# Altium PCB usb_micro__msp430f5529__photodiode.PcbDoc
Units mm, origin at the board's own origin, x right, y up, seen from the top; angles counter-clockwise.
Board outline 62 x 34 mm, 2 copper layers (Top, Bottom), stack 0 mm thick; 25 components, 18 nets, 155 pads, 46 vias.
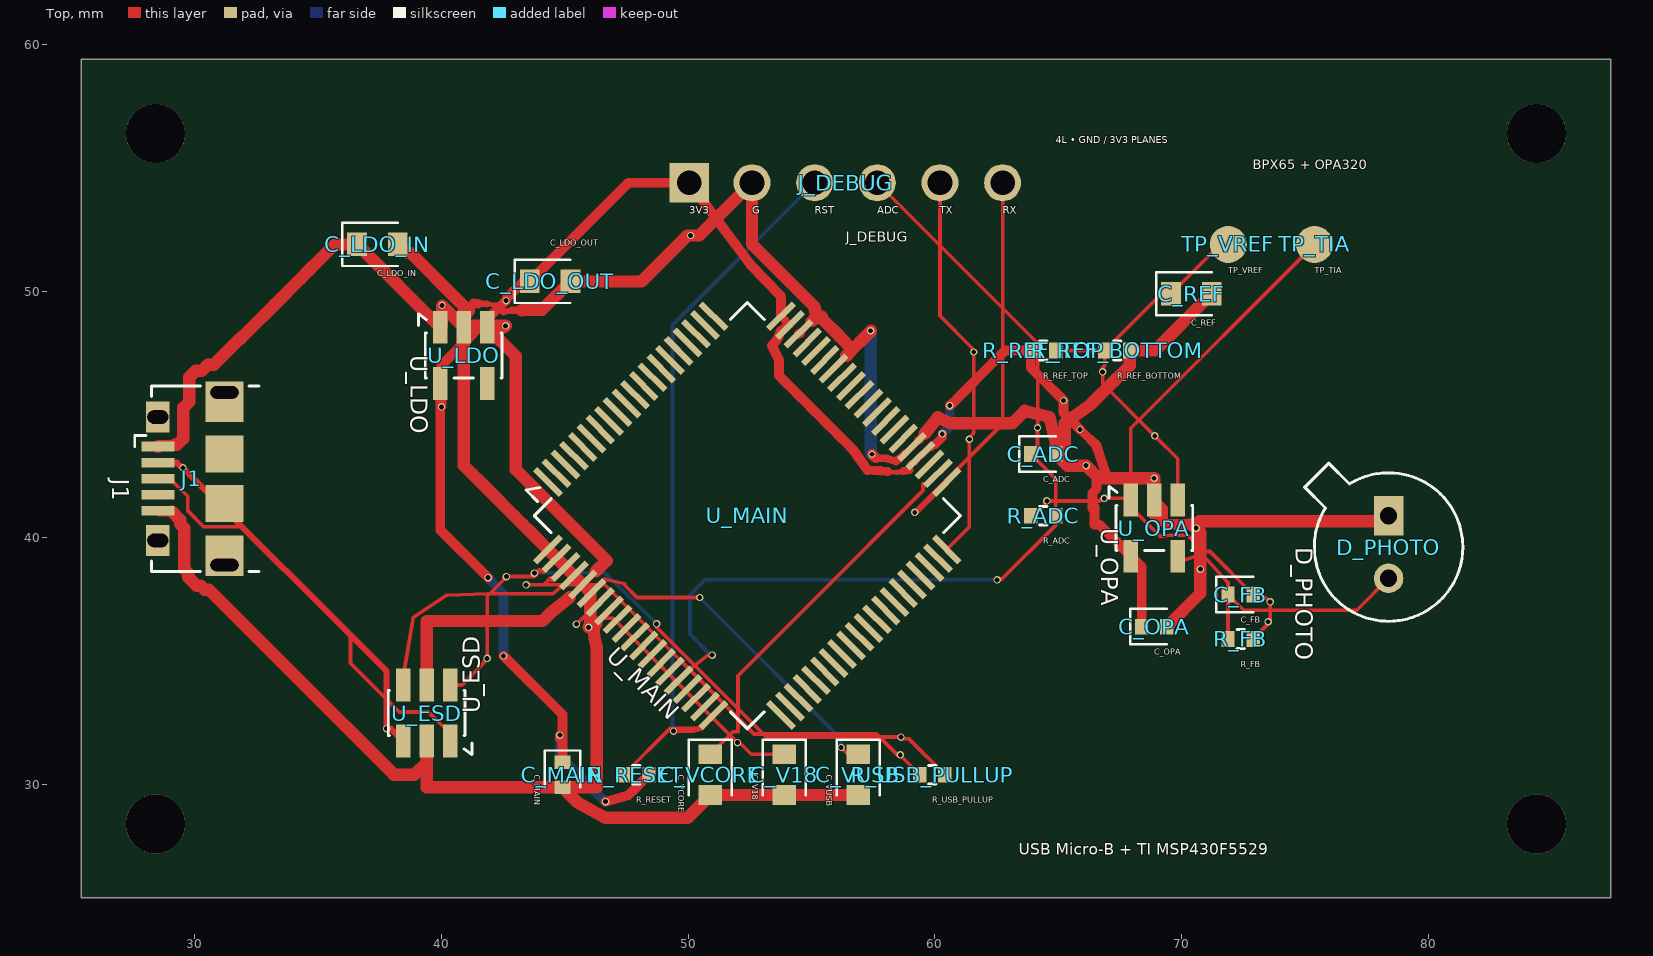
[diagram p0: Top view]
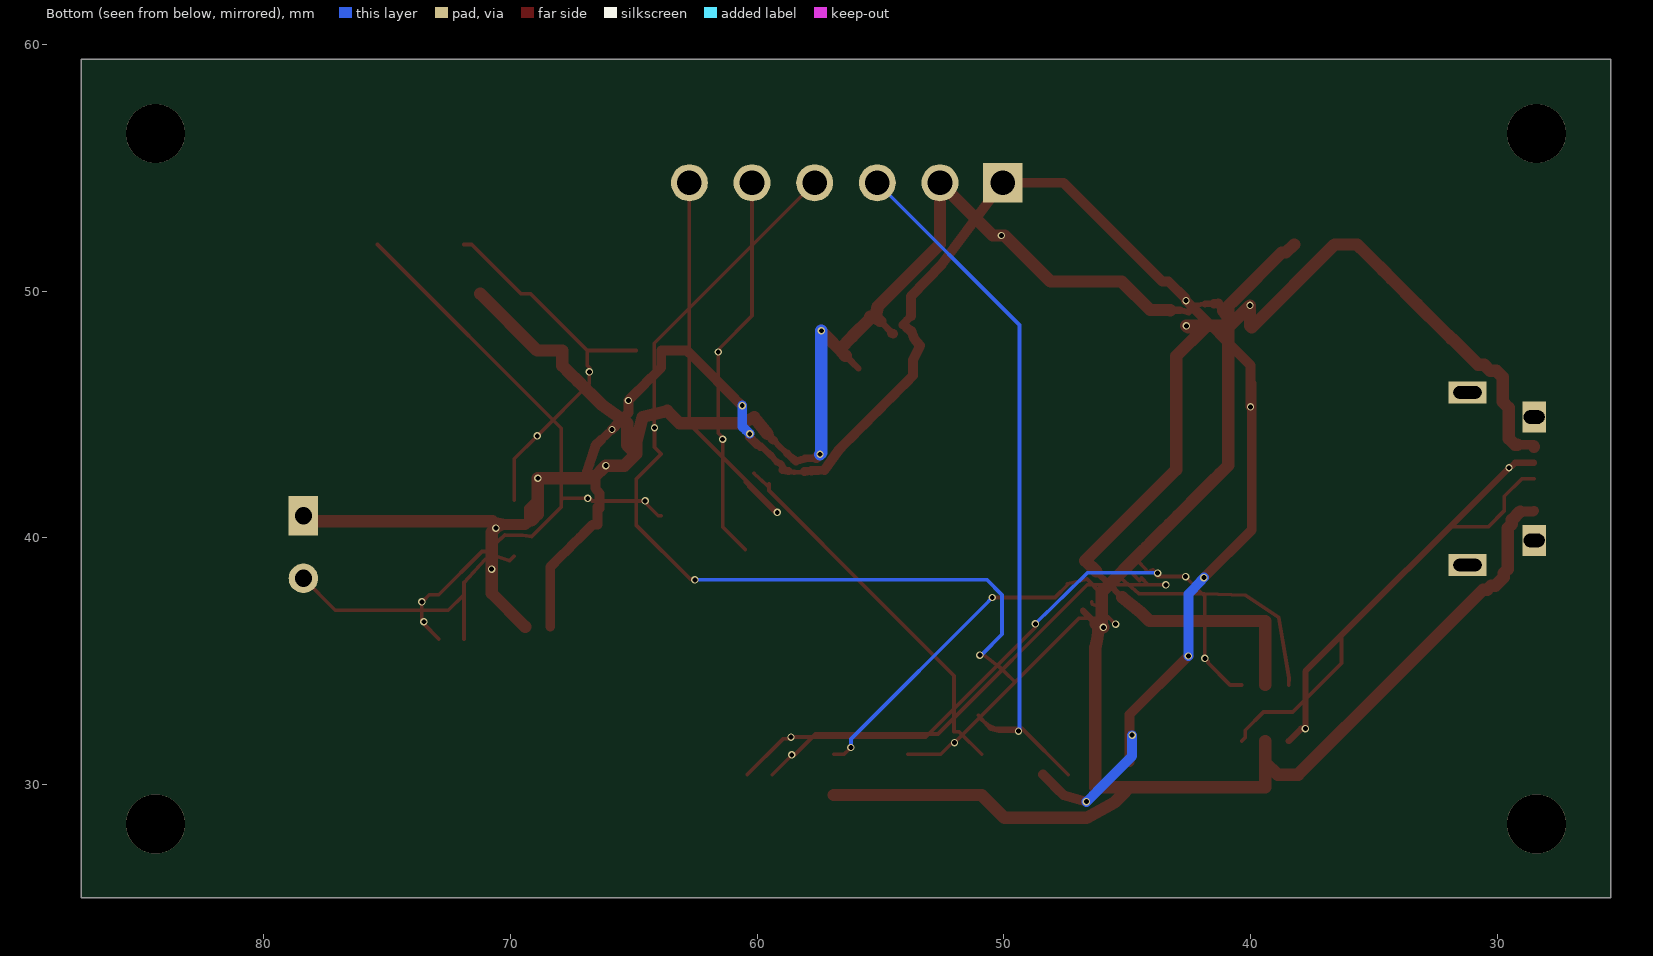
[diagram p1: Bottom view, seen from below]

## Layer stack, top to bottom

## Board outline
25.4,59.4 87.4,59.4 87.4,25.4 25.4,25.4

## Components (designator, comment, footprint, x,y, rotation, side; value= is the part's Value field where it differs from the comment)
C_ADC "" TSCIRCUIT-1.5600x0.6400mm 64.4,43.4 r0 top
C_FB "" TSCIRCUIT-1.5600x0.6400mm 72.4,37.7 r0 top
C_LDO_IN "" TSCIRCUIT-2.4500x0.9500mm 37.4,51.9 r0 top
C_LDO_OUT "" TSCIRCUIT-2.4500x0.9500mm 44.4,50.4 r0 top
C_MAIN "" TSCIRCUIT-0.6400x1.5600mm 44.9,30.4 r270 top
C_OPA "" TSCIRCUIT-1.5600x0.6400mm 68.9,36.4 r0 top
C_REF "" TSCIRCUIT-2.4500x0.9500mm 70.4,49.9 r0 top
C_V18 "" TSCIRCUIT-0.9500x2.4500mm 53.9,30.4 r270 top
C_VCORE "" TSCIRCUIT-0.9500x2.4500mm 50.9,30.4 r270 top
C_VUSB "" TSCIRCUIT-0.9500x2.4500mm 56.9,30.4 r270 top
D_PHOTO "" TSCIRCUIT-1.2000x3.9400mm 78.4,39.73 r270 top
J1 "" TSCIRCUIT-4.1500x7.8900mm 29.9,42.4 r270 top
J_DEBUG "" TSCIRCUIT-14.2000x1.5000mm 56.4,54.4 r0 top
R_ADC "" TSCIRCUIT-1.5600x0.6400mm 64.4,40.9 r0 top
R_FB "" TSCIRCUIT-1.5600x0.6400mm 72.4,35.9 r0 top
R_REF_BOTTOM "" TSCIRCUIT-1.5600x0.6400mm 67.4,47.6 r0 top
R_REF_TOP "" TSCIRCUIT-1.5600x0.6400mm 64.4,47.6 r0 top
R_RESET "" TSCIRCUIT-1.5600x0.6400mm 47.9,30.4 r0 top
R_USB_PULLUP "" TSCIRCUIT-1.5600x0.6400mm 59.9,30.4 r0 top
TP_TIA "" TSCIRCUIT-1.5000x1.5000mm 75.4,51.9 r0 top
TP_VREF "" TSCIRCUIT-1.5000x1.5000mm 71.9,51.9 r0 top
U_ESD "" TSCIRCUIT-2.5000x3.6000mm#1 39.4,32.9 r90 top
U_LDO "" TSCIRCUIT-2.5000x3.6000mm#2 40.9,47.4 r270 top
U_MAIN "" TSCIRCUIT-17.3948x17.3948mm 52.4,40.9 r315 top
U_OPA "" TSCIRCUIT-2.5000x3.6000mm#2 68.9,40.4 r270 top

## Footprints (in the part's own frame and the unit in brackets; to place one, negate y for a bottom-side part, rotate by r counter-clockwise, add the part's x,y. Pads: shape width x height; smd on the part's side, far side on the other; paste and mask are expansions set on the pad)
TSCIRCUIT-0.6400x1.5600mm [mm]
  rect 0.54x0.64 smd: 1(-0.51,0) 2(0.51,0)
  silkscreen extent -0.98,-0.72 0.51,0.72
TSCIRCUIT-0.9500x2.4500mm [mm]
  rect 0.8x0.95 smd: 1(-0.825,0) 2(0.825,0)
  silkscreen extent -1.43,-0.87 0.82,0.88
TSCIRCUIT-1.2000x3.9400mm [mm]
  rect 1.6x1.2 hole 0.7: 1(-1.17,0)
  round 1.2 hole 0.7: 2(1.37,0)
  silkscreen extent -3.3,-3.4 3.11,3.01
TSCIRCUIT-1.5000x1.5000mm [mm]
  round 1.5 smd: 1(0,0)
TSCIRCUIT-1.5600x0.6400mm [mm]
  rect 0.54x0.64 smd: 1(-0.51,0) 2(0.51,0)
  silkscreen extent -0.98,-0.72 0.51,0.72
TSCIRCUIT-2.4500x0.9500mm [mm]
  rect 0.8x0.95 smd: 1(-0.825,0) 2(0.825,0)
  silkscreen extent -1.42,-0.87 0.83,0.87
TSCIRCUIT-2.5000x3.6000mm#1 [mm]
  rect 1.325x0.6 smd: 1(-1.138,-0.95) 2(-1.138,0) 3(-1.138,0.95) 4(1.138,0.95) 5(1.138,0) 6(1.138,-0.95)
  silkscreen extent -1.69,-1.84 0.91,1.56
TSCIRCUIT-2.5000x3.6000mm#2 [mm]
  rect 1.325x0.6 smd: 1(-1.138,-0.95) 2(-1.138,0) 3(-1.138,0.95) 4(1.137,0.95) 5(1.137,-0.95)
  silkscreen extent -1.69,-1.84 0.91,1.56
TSCIRCUIT-4.1500x7.8900mm [mm]
  rect 0.89x1.55 hole 0.5 slot 1.15 at 90 deg: 1(-3.5,1.3) 1(3.5,1.3)
  rect 1.45x1.55 smd: 1(-3.025,1.3) 1(3.025,1.3)
  rect 1.25x0.95 hole 0.55 slot 0.85 at 90 deg: 1(-2.5,-1.4) 1(2.5,-1.4)
  rect 0.4x1.35 smd: 1(-1.3,-1.4) 2(-0.65,-1.4) 3(0,-1.4) 4(0.65,-1.4) 5(1.3,-1.4)
  rect 1.5x1.55 smd: 1(-1,1.3) 1(1,1.3)
  silkscreen extent -3.76,-2.34 3.76,2.69
TSCIRCUIT-14.2000x1.5000mm [mm]
  rect 1.6x1.6 hole 1: 1(-6.35,0)
  round 1.5 hole 1: 2(-3.81,0) 3(-1.27,0) 4(1.27,0) 5(3.81,0) 6(6.35,0)
TSCIRCUIT-17.3948x17.3948mm [mm]
  rect 1.475x0.25 smd: 1(-6.687,-4.75) 2(-6.687,-4.25) 3(-6.687,-3.75) 4(-6.687,-3.25) 5(-6.687,-2.75) 6(-6.687,-2.25) 7(-6.687,-1.75) 8(-6.687,-1.25) 9(-6.687,-0.75) 10(-6.687,-0.25) 11(-6.687,0.25) 12(-6.687,0.75) 13(-6.687,1.25) 14(-6.687,1.75) 15(-6.687,2.25) 16(-6.687,2.75) 17(-6.687,3.25) 18(-6.687,3.75) 19(-6.687,4.25) 20(-6.687,4.75) 41(6.688,4.75) 42(6.687,4.25) 43(6.687,3.75) 44(6.687,3.25) 45(6.688,2.75) 46(6.687,2.25) 47(6.687,1.75) 48(6.687,1.25) 49(6.687,0.75) 50(6.687,0.25) 51(6.687,-0.25) 52(6.687,-0.75) 53(6.687,-1.25) 54(6.687,-1.75) 55(6.687,-2.25) 56(6.687,-2.75) 57(6.687,-3.25) 58(6.687,-3.75) 59(6.687,-4.25) 60(6.687,-4.75)
  rect 0.25x1.475 smd: 21(-4.75,6.688) 22(-4.25,6.687) 23(-3.75,6.687) 24(-3.25,6.688) 25(-2.75,6.688) 26(-2.25,6.687) 27(-1.75,6.687) 28(-1.25,6.688) 29(-0.75,6.688) 30(-0.25,6.687) 31(0.25,6.687) 32(0.75,6.688) 33(1.25,6.688) 34(1.75,6.687) 35(2.25,6.687) 36(2.75,6.688) 37(3.25,6.688) 38(3.75,6.687) 39(4.25,6.687) 40(4.75,6.688) 61(4.75,-6.687) 62(4.25,-6.687) 63(3.75,-6.687) 64(3.25,-6.687) 65(2.75,-6.687) 66(2.25,-6.687) 67(1.75,-6.687) 68(1.25,-6.687) 69(0.75,-6.687) 70(0.25,-6.687) 71(-0.25,-6.687) 72(-0.75,-6.687) 73(-1.25,-6.687) 74(-1.75,-6.687) 75(-2.25,-6.687) 76(-2.75,-6.687) 77(-3.25,-6.687) 78(-3.75,-6.687) 79(-4.25,-6.687) 80(-4.75,-6.687)
  silkscreen extent -7.09,-6.11 6.11,6.11

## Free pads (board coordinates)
  round 2.4 hole 2.4 unplated: NPTH-1(28.4,28.4) NPTH-2(84.4,56.4) NPTH-3(84.4,28.4) NPTH-4(28.4,56.4)

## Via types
v1: diameter 0.3, hole 0.2, Top to Bottom, 46 vias

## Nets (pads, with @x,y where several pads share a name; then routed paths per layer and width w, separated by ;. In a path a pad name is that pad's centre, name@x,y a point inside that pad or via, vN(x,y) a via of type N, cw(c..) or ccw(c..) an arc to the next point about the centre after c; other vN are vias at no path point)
ADC_IN: C_ADC.1 J_DEBUG.4 R_ADC.2 U_MAIN.65 | length 37.7
  Top w0.15: U_MAIN.65 50.157,34.748 50.812,35.246 v1(50.972,35.246) ; J_DEBUG.4 64.179,47.891 64.179,44.528 64.179,44.481 v1(64.164,44.466) 64.164,43.674 C_ADC.1 64.91,42.38 R_ADC.2 64.91,40.526 62.719,38.336 62.562,38.336 v1(62.527,38.301)
  Bottom w0.15: v1(50.972,35.246) 50.941,35.277 50.888,35.277 50.073,36.091 50.073,37.689 50.686,38.301 v1(62.527,38.301)
GND: C_ADC.2 C_LDO_IN.2 C_LDO_OUT.2 C_MAIN.2 C_OPA.2 C_REF.2 C_V18.2 C_VCORE.2 C_VUSB.2 D_PHOTO.1 J1.5 J_DEBUG.2 R_REF_BOTTOM.2 U_ESD.2 U_LDO.2 U_MAIN.23 U_MAIN.27 U_MAIN.36 U_MAIN.73 U_MAIN.80 U_OPA.2 | length 142.4
  Top w0.2: 41.842,49.489 42.2,49.45 42.5,49.15
  Top w0.25: 42.5,49.15 42.852,49.232 ; 44.224,39.618 U_MAIN.80 ; U_MAIN.73@46.275,36.543 U_MAIN.73 ; U_MAIN.23 U_MAIN.23@54.982,48.785 ; U_MAIN.27@56.162,47.126 U_MAIN.27 U_MAIN.27@56.413,47.388 ; U_MAIN.36@58.794,43.428 U_MAIN.36 U_MAIN.36@59.339,43.95
  Top w0.251: U_MAIN.23@54.544,48.299 54.601,48.367 54.899,48.665 U_MAIN.23@55.017,48.783
  Top w0.257: U_MAIN.73@46.275,36.524 46.533,36.779 U_MAIN.73
  Top w0.275: 41.482,49.492 41.842,49.489
  Top w0.278: U_MAIN.27@56.162,47.126 56.432,47.386
  Top w0.3: 42.852,49.232 43.259,49.236
  Top w0.314: U_MAIN.36@58.526,43.188 U_MAIN.36@58.794,43.428
  Top w0.325: 57.597,43.248 58.056,43.21 58.431,43.103 58.526,43.188
  Top w0.345: U_MAIN.36@59.339,43.95 59.35,43.95 U_MAIN.36@59.525,44.15
  Top w0.375: 41.103,49.218 41.306,49.525 41.482,49.492 ; 69.247,40.681 69.525,40.525 69.994,40.525
  Top w0.389: U_MAIN.23 U_MAIN.23@54.544,48.299
  Top w0.397: U_MAIN.36@59.525,44.15 U_MAIN.36@59.581,44.219
  Top w0.4: J1.5 28.533,41.067 J1.5@29.067,41.067 ; U_OPA.2 69.247,41.19 69.247,40.936 69.247,40.681 ; 69.994,40.525 70.736,40.681
  Top w0.425: v1(57.456,43.392) 57.597,43.248
  Top w0.437: U_MAIN.23@54.982,48.785 55.029,48.785 55.416,48.963 ; 69.15,40.712 69.416,40.541 70.291,40.541
  Top w0.45: 70.291,40.541 v1(70.6,40.4)
  Top w0.475: 55.017,48.783 55.197,48.963
  Top w0.5: J1.5@29.067,41.067 29.4,40.733 29.4,40.567 29.567,40.4 29.567,38.733 29.733,38.567 29.733,38.4 30.067,38.067 30.233,38.067 30.4,37.9 30.567,37.9 34.129,34.337 38.067,30.4 38.9,30.4 39.4,30.9 U_ESD.2 39.4,29.89 C_MAIN.2 ; C_LDO_IN.2 38.565,51.571 38.729,51.571 40.65,49.65 40.9,49.4 U_LDO.2 ; 41.103,49.218 40.9,48.91 U_LDO.2 ; 43.259,49.236 43.665,49.241 44.066,49.241 C_LDO_OUT.2 48.106,50.4 49.968,52.262 v1(50.1,52.262) 50.452,52.262 J_DEBUG.2 52.59,51.905 55.112,49.383 55.197,48.963 ; 44.224,39.618 43.971,39.871 43.63,40.212 43.289,40.554 42.947,40.895 42.606,41.236 42.265,41.577 41.924,41.919 41.582,42.26 41.241,42.601 40.9,42.942 40.9,43.409 40.9,43.875 40.9,44.341 40.9,44.807 40.9,45.274 40.9,45.74 40.9,46.206 40.9,46.672 40.9,47.139 40.9,47.605 40.9,48.071 U_LDO.2 ; U_MAIN.80 46.025,37.817 46.025,36.4 v1(45.965,36.374) 46.275,36.525 U_MAIN.73@46.275,36.543 ; 46.275,36.524 46.15,36.4 46.206,35.957 46.292,35.566 46.299,35.097 46.299,29.89 C_MAIN.2 ; 55.416,48.963 55.416,48.897 56.152,48.161 56.65,47.65 56.432,47.386 ; 56.413,47.388 57.4,48.375 v1(57.4,48.4) ; C_VUSB.2 C_V18.2 C_VCORE.2 49.975,28.65 46.65,28.65 45.513,29.273 45.206,29.581 C_MAIN.2 ; 59.581,44.219 60.126,44.887 60.65,44.65 63.15,44.65 63.65,45.15 64.65,44.9 64.91,43.825 C_ADC.2 ; 69.15,40.712 68.9,40.963 U_OPA.2 68.9,42.411 v1(68.893,42.418) 66.651,42.418 v1(66.139,42.93) 65.38,42.93 C_ADC.2 ; C_OPA.2 70.766,37.756 v1(70.766,38.733) 70.766,40.234 v1(70.6,40.4) ; 70.736,40.681 71.232,40.681 71.729,40.681 72.225,40.681 72.721,40.681 73.218,40.681 73.714,40.681 74.21,40.681 74.707,40.681 75.203,40.681 75.699,40.681 76.196,40.681 76.692,40.681 77.189,40.681 77.685,40.681 78.181,40.681 D_PHOTO.1 ; C_REF.2 68.925,47.6 R_REF_BOTTOM.2 67.909,47.292 67.908,46.983 67.589,46.67 67.271,46.357 66.953,46.043 66.634,45.73 66.316,45.416 65.275,44.65 65.275,43.765 C_ADC.2
  Bottom w0.5: v1(57.4,48.4) 57.4,47.914 57.4,47.428 57.4,46.942 57.4,46.457 57.4,45.971 57.4,45.485 57.4,44.999 57.4,44.513 57.4,44.027 57.4,43.542 57.4,43.448 v1(57.456,43.392)
MAIN_RESET: J_DEBUG.3 R_RESET.1 U_MAIN.61 | length 31.2
  Top w0.15: R_RESET.1 49.264,32.274 50.358,32.274 50.359,32.286 50.578,32.38 50.983,32.67 50.96,32.742 U_MAIN.61 50.533,32.248 50.205,32.164 v1(49.406,32.164)
  Bottom w0.15: v1(49.406,32.164) 49.365,32.205 49.365,32.289 49.365,48.635 J_DEBUG.3
MSP_USB_PUR: R_USB_PULLUP.1 U_MAIN.78 | length 21.2
  Top w0.15: U_MAIN.78 44.499,38.26 44.42,38.372 44.147,38.1 43.558,38.1 v1(43.428,38.094) 46.62,38.1 52.67,32.051 57.634,32.051 58.485,31.2 v1(58.6,31.2) 58.6,31.19 R_USB_PULLUP.1
MSP_V18: C_V18.1 U_MAIN.74 | length 12.2
  Top w0.15: U_MAIN.74 46.419,37.31 46.234,37.249 45.796,36.808 v1(45.466,36.502) 45.585,36.597 45.585,36.608 45.723,36.747 45.765,36.747 46.95,36.747 v1(52,31.697) 52.004,31.693 52.094,31.693 52.562,31.225 C_V18.1
MSP_VCORE: C_VCORE.1 U_MAIN.39 | length 15.5
  Top w0.15: C_VCORE.1 51.817,32.142 52.019,32.142 52.019,34.414 55.12,37.515 59.523,41.918 59.525,42.184 59.58,42.116 U_MAIN.39
MSP_VUSB: C_VUSB.1 U_MAIN.75 | length 14.2
  Top w0.15: U_MAIN.75 46.625,38.332 47.415,38.135 47.412,38.101 47.929,37.583 v1(50.469,37.583) ; v1(56.2,31.5) 56.244,31.456 56.246,31.456 56.476,31.225 C_VUSB.1
  Bottom w0.15: v1(50.469,37.583) 50.613,37.439 50.613,37.435 56.2,31.848 v1(56.2,31.5)
PD_SUM: C_FB.1 D_PHOTO.2 R_FB.1 U_OPA.4 | length 12.2
  Top w0.15: U_OPA.4 70.041,39.072 70.575,39.25 71.025,39.138 71.89,38.188 C_FB.1 ; R_FB.1 C_FB.1 ; D_PHOTO.2 77.106,37.065 72.627,37.063 72.524,37.066 C_FB.1
TIA_OUT: C_FB.2 R_ADC.1 R_FB.2 TP_TIA.1 U_OPA.1 | length 27.2
  Top w0.15: R_ADC.1 64.016,40.9 64.457,41.341 64.457,41.412 v1(64.544,41.499) 66.679,41.499 66.76,41.58 66.823,41.58 v1(66.871,41.603) 67.884,41.603 U_OPA.1 ; R_FB.2 73.515,36.505 v1(73.515,36.601) 73.557,36.643 73.557,36.669 73.6,36.713 v1(73.6,37.404) 73.556,37.444 73.554,37.444 73.298,37.7 C_FB.2 71.159,39.451 70.959,39.451 70.233,40.114 69.515,40.107 69.141,40.058 67.95,41.249 U_OPA.1 ; TP_TIA.1 67.95,44.45 U_OPA.1
UART_MAIN_RX: J_DEBUG.6 U_MAIN.40 | length 16.7
  Top w0.15: U_MAIN.40 60.339,42.122 60.342,42.08 59.292,41.036 v1(59.188,41.036) 59.234,41.081 59.234,41.106 62.75,44.622 J_DEBUG.6
UART_MAIN_TX: J_DEBUG.5 U_MAIN.41 | length 15.9
  Top w0.15: J_DEBUG.5 60.21,49.005 61.521,47.693 61.521,47.597 v1(61.58,47.538) 61.58,44.253 61.429,44.102 61.429,44.029 v1(61.4,44) 61.4,40.442 U_MAIN.41
USB_DM_MCU: U_ESD.4 U_MAIN.77 | length 9.8
  Top w0.15: U_ESD.4 38.439,34.311 38.85,36.775 40.2,37.675 41.886,37.74 44.526,37.738 U_MAIN.77
USB_DM_PORT: J1.2 U_ESD.3 | length 16
  Top w0.25: J1.2 29.273,43.05 29.433,42.89 29.471,42.89 v1(29.516,42.845) 37.775,34.586 37.775,32.379 v1(37.775,32.265) 37.947,32.265 U_ESD.3
USB_DP_MCU: R_USB_PULLUP.2 U_ESD.6 U_MAIN.79 | length 29.4
  Top w0.15: U_ESD.6 40.825,34.038 41.726,34.938 41.726,34.99 v1(41.85,35.114) 41.85,37.633 42.543,38.326 42.543,38.344 v1(42.629,38.432) 43.762,38.434 44.02,38.688 44.145,38.613 ; v1(43.765,38.572) 43.818,38.572 43.955,38.709 44.145,38.613 ; v1(48.723,36.516) 48.723,36.477 48.723,36.368 53.167,31.924 v1(58.631,31.924) 58.704,31.851 58.761,31.851 58.959,31.851 R_USB_PULLUP.2 ; 44.145,38.613 U_MAIN.79 44.145,38.613
  Bottom w0.15: v1(43.765,38.572) 43.776,38.583 43.888,38.583 46.617,38.583 v1(48.723,36.516)
USB_DP_PORT: J1.3 U_ESD.1 | length 17.5
  Top w0.15: J1.3 28.994,42.4 29.705,41.689 29.705,41.11 30.352,40.454 31.962,40.459 36.306,36.115 36.306,34.919 38.288,32.937 39.472,32.937 40.209,32.201 40.209,31.903 U_ESD.1
VBUS5: C_LDO_IN.1 J1.1@28.5,43.7 U_ESD.5 U_LDO.1 U_LDO.3 U_MAIN.76 | length 44.5
  Top w0.25: U_MAIN.76@45.275,37.65 U_MAIN.76 U_MAIN.76@46.248,38.637
  Top w0.273: U_MAIN.76@45.205,37.594 U_MAIN.76@45.275,37.65
  Top w0.4: J1.1@28.525,43.725 28.525,43.775 29.175,43.775
  Top w0.5: J1.1@28.5,43.7 J1.1@28.525,43.725 ; 29.175,43.775 29.275,43.775 29.525,44.025 29.525,45.275 29.775,45.525 29.775,46.525 30.025,46.775 30.275,46.775 30.525,47.025 30.775,47.025 31.83,48.08 31.854,48.08 32.202,48.427 32.549,48.774 32.896,49.122 33.243,49.469 33.591,49.816 33.938,50.164 34.285,50.511 34.633,50.858 34.98,51.205 35.327,51.553 35.674,51.9 36.125,51.9 C_LDO_IN.1 36.588,51.9 U_LDO.1 40.02,48.608 v1(40.02,49.427) 40.847,48.6 v1(42.6,48.6) 42.59,48.59 42.578,48.59 42.526,48.538 U_LDO.3 43.011,47.377 43.011,42.768 46.702,39.077 46.688,39.077 46.248,38.637 ; U_ESD.5 39.4,36.63 44.092,36.63 44.437,36.975 U_MAIN.76@45.205,37.594
VCC_3V3: C_LDO_OUT.1 C_MAIN.1 C_OPA.1 J_DEBUG.1 R_REF_TOP.1 R_RESET.2 U_LDO.5 U_MAIN.21 U_MAIN.22 U_MAIN.37 U_OPA.5 | length 78
  Top w0.2: 58.09,42.701 58.15,42.663 58.5,42.663
  Top w0.212: 58.5,42.663 58.74,42.704
  Top w0.25: U_MAIN.21 53.858,48.899 ; U_MAIN.37@59.226,43.093 U_MAIN.37 ; U_MAIN.37@59.838,43.727 59.875,43.652 U_MAIN.37@60.012,43.789
  Top w0.277: U_MAIN.37 59.633,43.529 U_MAIN.37@59.838,43.727
  Top w0.288: U_MAIN.37@58.981,42.746 58.895,42.763 59.043,43.001 U_MAIN.37@59.226,43.093
  Top w0.312: U_MAIN.22@53.933,48.508 U_MAIN.22 ; 53.947,48.811 U_MAIN.22
  Top w0.325: 53.858,48.899 53.947,48.811 ; 58.74,42.704 U_MAIN.37@58.981,42.746
  Top w0.337: v1(65.887,44.395) 66.11,44.181 66.332,43.967
  Top w0.363: 57.804,42.723 58.09,42.701 ; U_MAIN.37@60.012,43.789 60.09,43.866 60.304,44.081 v1(60.304,44.222)
  Top w0.375: 57.275,42.75 57.539,42.737 57.804,42.723
  Top w0.4: v1(41.888,38.39) 39.95,40.328 U_LDO.5 40,46.212 v1(40,45.316) 40,45.345 40,47 v1(42.613,49.619) 42.624,49.63 42.621,49.7 43.322,50.4 C_LDO_OUT.1 47.575,54.4 J_DEBUG.1 52.5,51.1 53.77,49.788 53.77,49.688 53.77,49.588 53.77,49.488 53.77,49.388 53.77,49.317 53.77,49.288 53.77,49.188 53.77,49.088 U_MAIN.21 ; v1(42.516,35.211) 42.546,35.181 42.557,35.181 44.9,32.838 C_MAIN.1 44.9,31.196 44.9,31.482 44.9,31.768 44.8,31.868 v1(44.8,32) ; v1(46.651,29.305) 47.583,29.573 47.858,29.849 48.134,30.124 R_RESET.2 ; U_MAIN.22@53.933,48.508 53.743,48.382 53.631,48.076 53.4,47.8 53.679,47.207 53.68,46.895 53.681,46.582 53.955,46.308 54.229,46.034 54.503,45.76 54.777,45.486 55.051,45.212 55.325,44.938 55.599,44.664 55.873,44.39 56.147,44.116 56.422,43.842 56.696,43.568 57.275,42.75 ; v1(60.606,45.365) 60.719,45.478 60.734,45.478 60.999,45.743 61.265,46.008 61.53,46.274 61.795,46.539 62.06,46.804 62.326,47.069 62.591,47.335 62.856,47.6 63.201,47.6 63.545,47.6 R_REF_TOP.1 63.89,47.253 63.89,46.907 64.145,46.652 64.401,46.396 64.656,46.141 64.912,45.885 65.167,45.63 v1(65.226,45.571) 65.226,45.322 65.226,45.073 65.492,44.808 65.757,44.542 65.757,44.525 v1(65.887,44.395) ; 66.332,43.967 66.555,43.753 66.8,43 66.9,42.7 66.553,42.36 66.552,42.012 66.4,41.8 66.4,41.2 66.472,41.25 66.475,40.891 66.478,40.532 66.68,40.532 66.934,40.278 67.188,40.024 67.442,39.77 67.696,39.516 U_OPA.5 68.39,38.822 C_OPA.1
  Bottom w0.4: v1(41.888,38.39) 42.002,38.276 42.002,38.247 42.516,37.733 v1(42.516,35.211) ; v1(44.8,32) 44.8,31.716 44.8,31.432 44.8,31.148 45.064,30.884 45.328,30.62 45.592,30.356 45.857,30.091 46.121,29.827 46.385,29.563 46.649,29.299 v1(46.651,29.305) ; v1(60.304,44.222) 60.318,44.236 60.462,44.38 60.606,44.524 60.606,44.804 60.606,45.085 v1(60.606,45.365)
VREF_0V5: C_REF.1 R_REF_BOTTOM.1 R_REF_TOP.2 TP_VREF.1 U_OPA.3 | length 16.1
  Top w0.15: R_REF_TOP.2 R_REF_BOTTOM.1 ; U_OPA.3 69.85,43.206 v1(68.92,44.136) 68.891,44.165 66.808,46.248 v1(66.808,46.732) 66.792,46.748 66.792,46.891 66.89,46.988 R_REF_BOTTOM.1 ; TP_VREF.1 71.575,51.9 C_REF.1 69.19,49.9 R_REF_BOTTOM.1
pads on no net: J1.1@28.5,39.9 J1.1@28.5,44.9 J1.1@31.2,38.9 J1.1@31.2,39.375 J1.1@31.2,41.4 J1.1@31.2,43.4 J1.1@31.2,45.9 J1.1@31.2,45.425 J1.4 U_LDO.4 U_MAIN.1 U_MAIN.2 U_MAIN.3 U_MAIN.4 U_MAIN.5 U_MAIN.6 U_MAIN.7 U_MAIN.8 U_MAIN.9 U_MAIN.10 U_MAIN.11 U_MAIN.12 U_MAIN.13 U_MAIN.14 U_MAIN.15 U_MAIN.16 U_MAIN.17 U_MAIN.18 U_MAIN.19 U_MAIN.20 U_MAIN.24 U_MAIN.25 U_MAIN.26 U_MAIN.28 U_MAIN.29 U_MAIN.30 U_MAIN.31 U_MAIN.32 U_MAIN.33 U_MAIN.34 U_MAIN.35 U_MAIN.38 U_MAIN.42 U_MAIN.43 U_MAIN.44 U_MAIN.45 U_MAIN.46 U_MAIN.47 U_MAIN.48 U_MAIN.49 U_MAIN.50 U_MAIN.51 U_MAIN.52 U_MAIN.53 U_MAIN.54 U_MAIN.55 U_MAIN.56 U_MAIN.57 U_MAIN.58 U_MAIN.59 U_MAIN.60 U_MAIN.62 U_MAIN.63 U_MAIN.64 U_MAIN.66 U_MAIN.67 U_MAIN.68 U_MAIN.69 U_MAIN.70 U_MAIN.71 U_MAIN.72

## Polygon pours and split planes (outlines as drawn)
GND on Mid1 (solid): 87.1,59.1 25.7,59.1 25.7,25.7 87.1,25.7
VCC_3V3 on Mid2 (solid): 87.1,59.1 25.7,59.1 25.7,25.7 87.1,25.7

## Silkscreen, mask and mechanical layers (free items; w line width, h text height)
Top Overlay:
  text "4L • GND / 3V3 PLANES" at 64.9,55.9 h0.48
  text "BPX65 + OPA320" at 72.9,54.8 h0.65
  text "USB Micro-B + TI MSP430F5529" at 63.4,27 h0.78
